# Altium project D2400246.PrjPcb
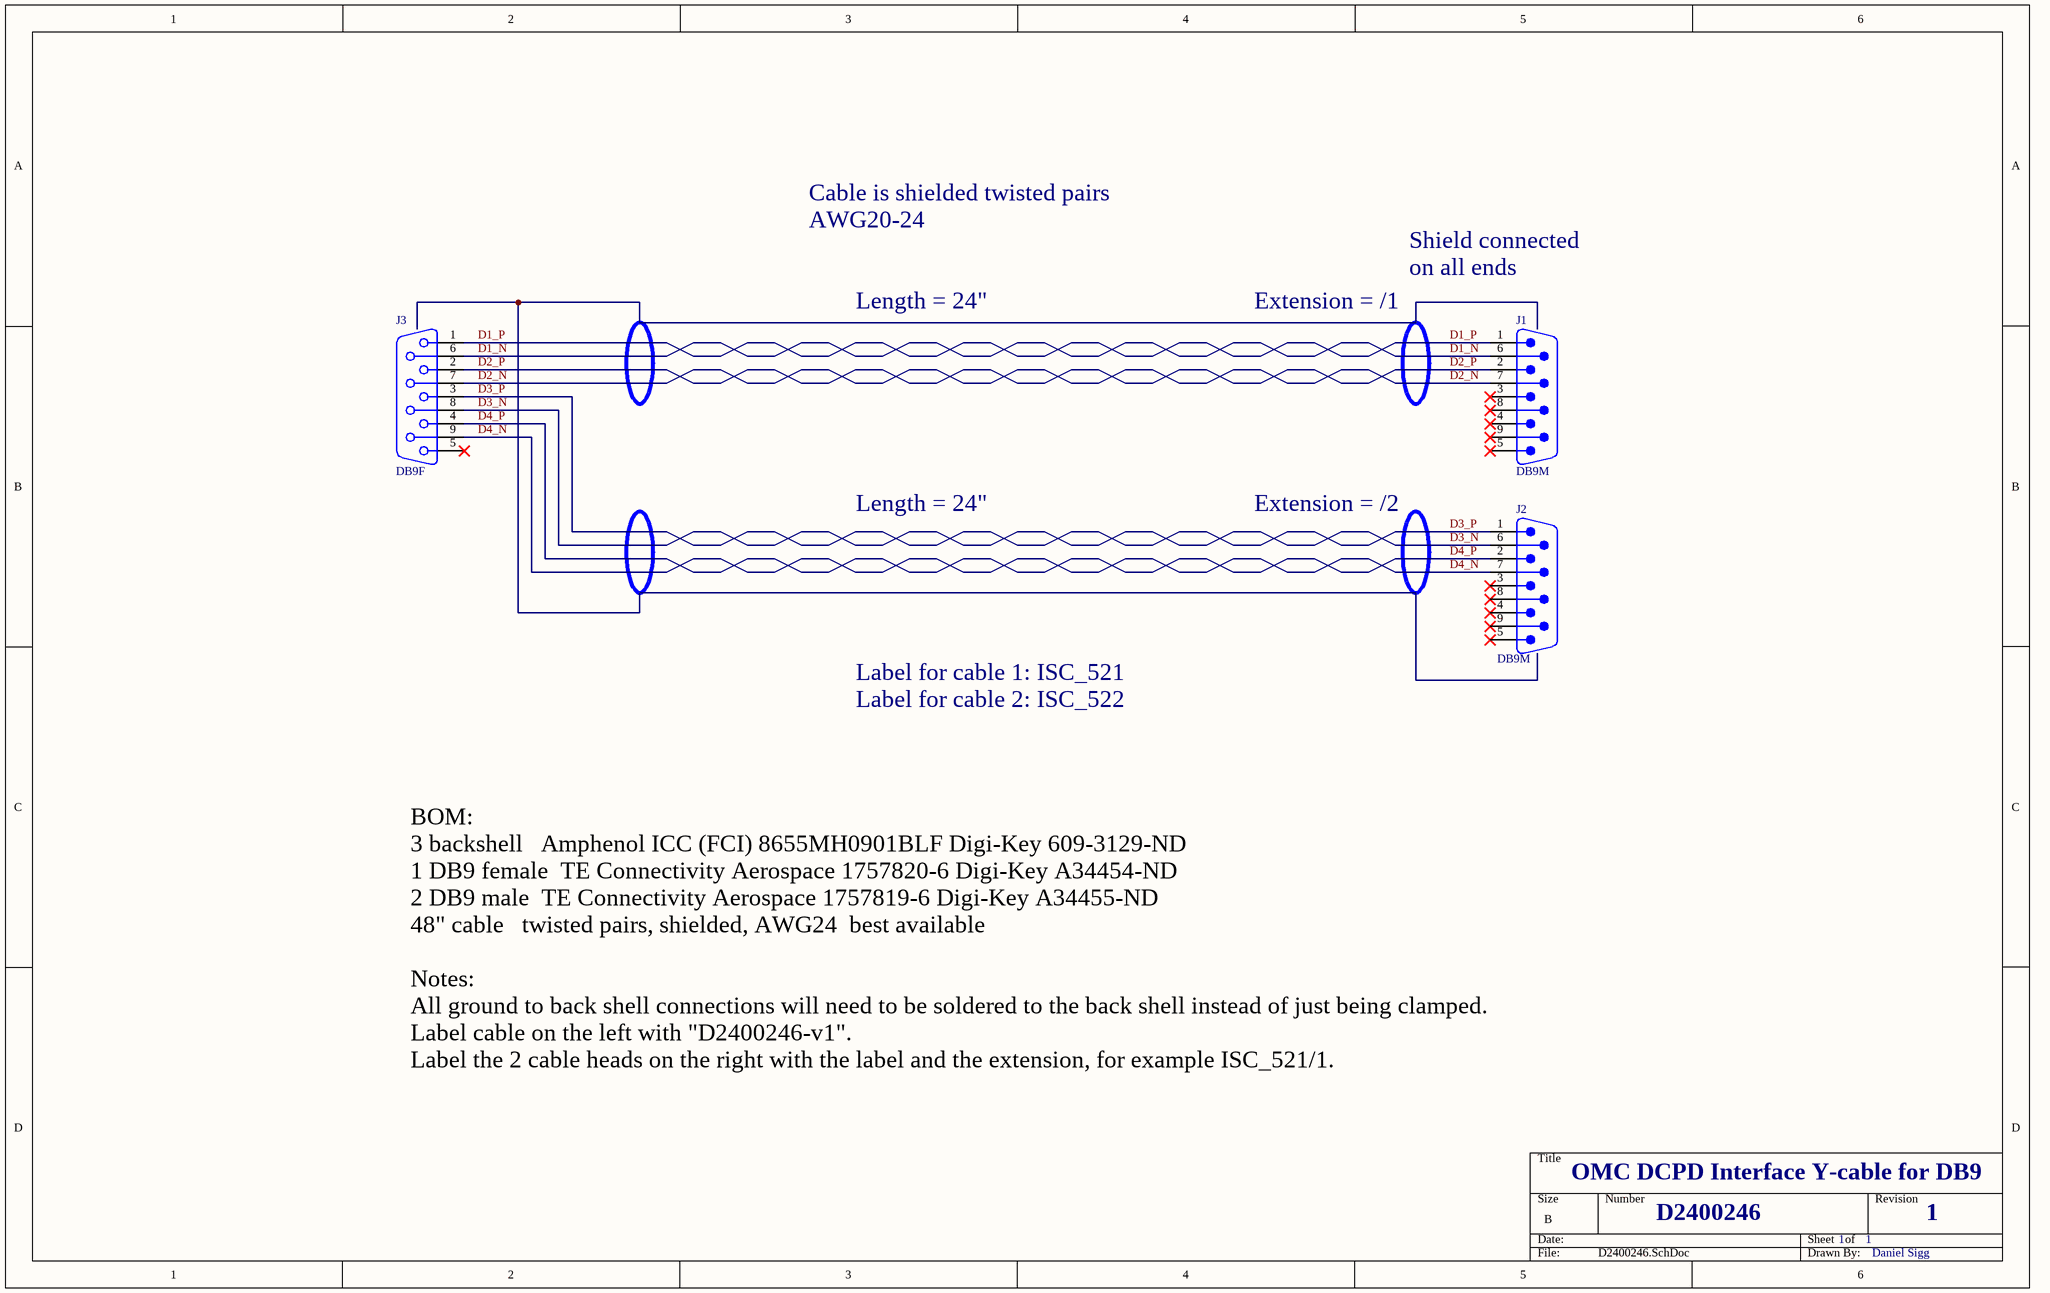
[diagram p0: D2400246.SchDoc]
1 sheet, 3 parts. Net scope: global (net labels, ports and power ports of the same name join across sheets).

## Sheet D2400246.SchDoc
size B; SheetNumber: 1; SheetTotal: 1; PageSetup: Record=PageOptions¦CenterHorizontal=True¦CenterVertical=True¦PrintScale=1.12¦XCorrection=1.00¦YCorrection=1.00¦PrintKind=0¦BorderSize=5000000¦LeftOffset=0¦BottomOffset=0¦Orientation=2¦PaperLength=1000¦PaperWidth=1000¦Scale=100¦PaperSource=7¦PrintQuality=-4¦MediaType=1¦DitherType=10¦PaperKind=Tabloid¦PrintScaleMode=1

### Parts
J1  DB9M  [DB9M-RA]
J2  DB9M  [DB9M-RA]
J3  DB9F  [DB9F-RA]

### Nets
D1_N: J1.6 J3.6
D1_P: J1.1 J3.1
D2_N: J1.7 J3.7
D2_P: J1.2 J3.2
D3_N: J2.6 J3.8
D3_P: J2.1 J3.3
D4_N: J2.7 J3.9
D4_P: J2.2 J3.4

Not connected (* = marked no-connect by the designer): J1 3* 4* 5* 8* 9* 10(MH1) 11(MH2); J2 3* 4* 5* 8* 9* 10(MH1) 11(MH2); J3 5* 10(MH1) 11(MH2)

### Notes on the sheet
- Cable is shielded twisted pairs
- AWG20-24
- Shield connected
- on all ends
- Length = 24"
- Extension = /1
- Extension = /2
- Label for cable 1: ISC_521
- Label for cable 2: ISC_522
- BOM:
  3	backshell 		Amphenol ICC (FCI) 8655MH0901BLF	Digi-Key 609-3129-ND
  1	DB9 female 	TE Connectivity Aerospace 1757820-6	Digi-Key A34454-ND
  2	DB9 male		TE Connectivity Aerospace 1757819-6	Digi-Key A34455-ND
  48"	cable 		twisted pairs, shielded, AWG24		best available
  Notes:
  All ground to back shell connections will need to be soldered to the back shell instead of just being clamped.
  Label cable on the left with "D2400246-v1".
  Label the 2 cable heads on the right with the label and the extension, for example ISC_521/1.
- OMC DCPD Interface Y-cable for DB9
- D2400246
- 1
- Daniel Sigg

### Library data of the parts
J1 J2 = DB9M: Plug Assembly, 9 Position, Right Angle, .318 Series; Part Number: A32094-ND
J3 = DB9F: Receptacle Assembly, 9 Position, Right Angle, .318 Series; Part Number: A32119-ND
